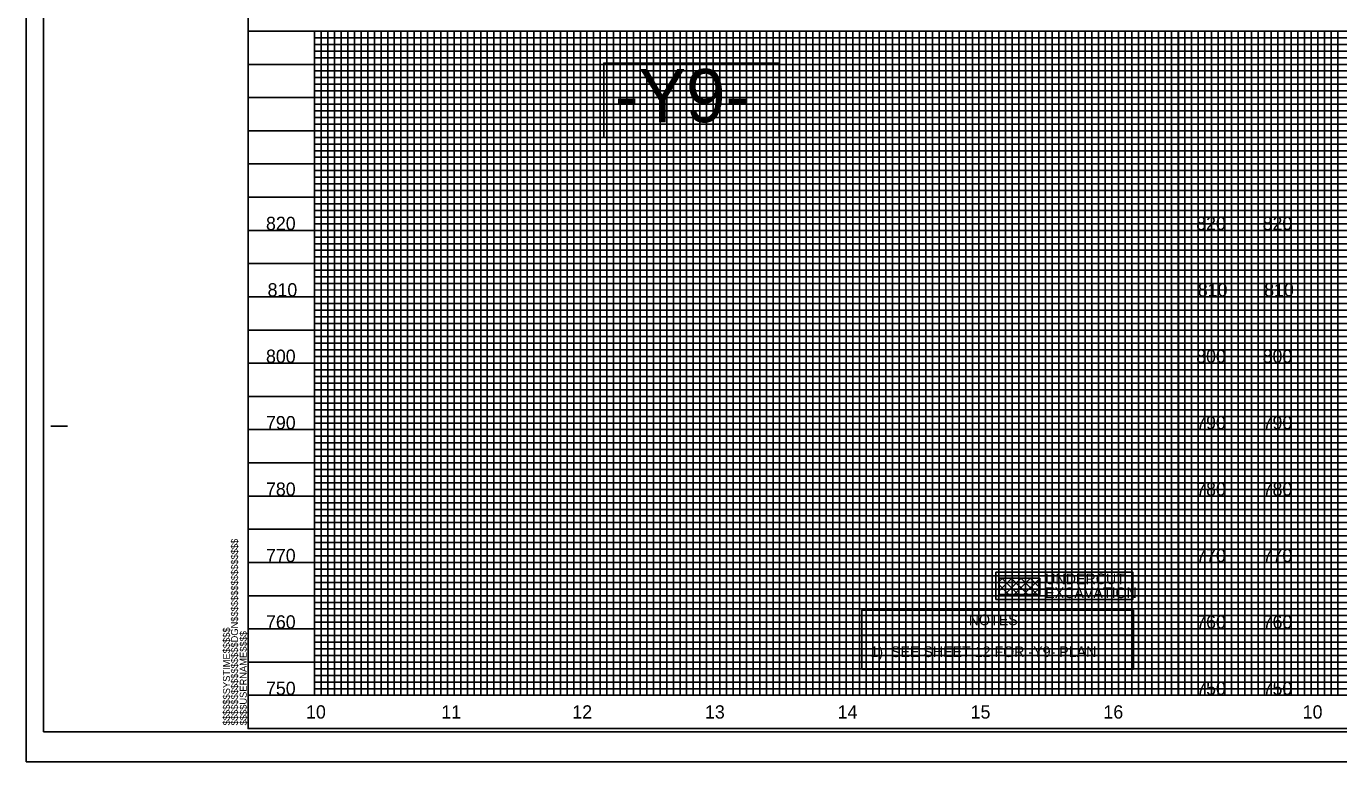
# Model space of a CAD drawing. Extents: x 600491 to 602382, y -54561 to -53461.
# Drawn here: x 600491 to 601479, y -54561 to -54007 of the extents above; entities that cross this region are included whole.
import ezdxf

# ---------------------------------------------------------------- set-up
doc = ezdxf.new("R2010")
doc.units = 0
for name, color, linetype in [('Default', 7, 'Continuous'), ('Exist Vertical Profile Horizontal Axis Label Major', 7, 'Continuous'), ('Exist Vertical Profile Vertical Axis Label', 7, 'Continuous'), ('Prop DSN Text', 7, 'Continuous'), ('Prop Grid Mask', 7, 'Continuous'), ('Prop VPI Label', 7, 'Continuous'), ('Prop XS Undercut Exc Hatch', 7, 'Continuous'), ('Prop XSC Text', 7, 'Continuous'), ('Sheet Cutting Line CELL', 7, 'Continuous'), ('Sheet DOT Grid CELL', 7, 'Continuous'), ('Sheet Layout Profile Border Port 2', 7, 'Continuous'), ('Sheet Plot Border Inside CELL', 7, 'Continuous'), ('Sheet Plot Border Outside CELL', 7, 'Continuous'), ('Sheet Profile CELL', 7, 'Continuous'), ('Sheet Profile Grid Major CELL', 7, 'Continuous'), ('Sheet Profile Grid Middle CELL', 7, 'Continuous'), ('Sheet Profile Grid Minor CELL', 7, 'Continuous')]:
    doc.layers.add(name, color=color, linetype=linetype)

msp = doc.modelspace()

# ---------------------------------------------------------------- linework, layer by layer
at = {"layer": 'Default'}
for points in [[(600708.27, -54010.99), (601358.32, -54010.99), (601358.32, -54510.99), (600708.27, -54510.99)], [(601458.32, -54010.99), (601708.27, -54010.99), (601708.27, -54510.99), (601458.32, -54510.99)]]:
    msp.add_lwpolyline(points, close=True, dxfattribs=at)
at = {"layer": 'Prop Grid Mask'}
for p, q in [((601358.32, -54035.99), (601408.32, -54035.99)), ((601408.32, -54035.99), (601458.32, -54035.99)), ((601358.32, -54060.99), (601408.32, -54060.99)), ((601408.32, -54060.99), (601458.32, -54060.99)), ((601358.32, -54085.99), (601408.32, -54085.99)), ((601408.32, -54085.99), (601458.32, -54085.99)), ((601358.32, -54110.99), (601408.32, -54110.99)), ((601408.32, -54110.99), (601458.32, -54110.99)), ((601358.32, -54135.99), (601408.32, -54135.99)), ((601408.32, -54135.99), (601458.32, -54135.99)), ((601358.32, -54160.99), (601408.32, -54160.99)), ((601408.32, -54160.99), (601458.32, -54160.99)), ((601358.32, -54185.99), (601408.32, -54185.99)), ((601408.32, -54185.99), (601458.32, -54185.99)), ((601358.32, -54210.99), (601408.32, -54210.99)), ((601408.32, -54210.99), (601458.32, -54210.99)), ((601358.32, -54235.99), (601408.32, -54235.99)), ((601408.32, -54235.99), (601458.32, -54235.99)), ((601358.32, -54260.99), (601408.32, -54260.99)), ((601408.32, -54260.99), (601458.32, -54260.99)), ((601358.32, -54285.99), (601408.32, -54285.99)), ((601408.32, -54285.99), (601458.32, -54285.99)), ((601358.32, -54310.99), (601408.32, -54310.99)), ((601408.32, -54310.99), (601458.32, -54310.99)), ((601358.32, -54335.99), (601408.32, -54335.99)), ((601408.32, -54335.99), (601458.32, -54335.99)), ((601358.32, -54360.99), (601408.32, -54360.99)), ((601408.32, -54360.99), (601458.32, -54360.99)), ((601358.32, -54385.99), (601408.32, -54385.99)), ((601408.32, -54385.99), (601458.32, -54385.99)), ((601358.32, -54410.99), (601408.32, -54410.99)), ((601408.32, -54410.99), (601458.32, -54410.99)), ((601358.32, -54435.99), (601408.32, -54435.99)), ((601408.32, -54435.99), (601458.32, -54435.99)), ((601358.32, -54460.99), (601408.32, -54460.99)), ((601408.32, -54460.99), (601458.32, -54460.99)), ((601358.32, -54485.99), (601408.32, -54485.99)), ((601408.32, -54485.99), (601458.32, -54485.99))]:
    msp.add_line(p, q, dxfattribs=at)
for points in [[(601358.32, -54010.99), (601408.32, -54010.99), (601408.32, -54510.99), (601358.32, -54510.99)], [(601408.32, -54010.99), (601458.32, -54010.99), (601458.32, -54510.99), (601408.32, -54510.99)], [(600925.94, -54091.06), (601057.96, -54091.06), (601057.96, -54035.01), (600925.94, -54035.01)], [(601221.02, -54418.33), (601324.1, -54418.33), (601324.1, -54438.8), (601221.02, -54438.8)], [(601223.44, -54435.15), (601253.95, -54435.15), (601253.95, -54422.82), (601223.44, -54422.82)], [(601120.11, -54491.28), (601324.46, -54491.28), (601324.46, -54446.99), (601120.11, -54446.99)], [(601120.11, -54465.71), (601324.46, -54465.71), (601324.46, -54446.99), (601120.11, -54446.99)]]:
    msp.add_lwpolyline(points, close=True, dxfattribs=at)
at = {"layer": 'Prop XS Undercut Exc Hatch'}
for p, q in [((601223.44, -54425.26), (601225.89, -54422.82)), ((601223.44, -54432.34), (601232.96, -54422.82)), ((601225.55, -54422.82), (601237.88, -54435.15)), ((601227.7, -54435.15), (601240.03, -54422.82)), ((601232.62, -54422.82), (601244.95, -54435.15)), ((601234.77, -54435.15), (601247.1, -54422.82)), ((601239.69, -54422.82), (601252.02, -54435.15)), ((601241.84, -54435.15), (601253.95, -54423.04)), ((601246.76, -54422.82), (601253.95, -54430)), ((601253.83, -54422.82), (601253.95, -54422.93)), ((601223.44, -54427.78), (601230.81, -54435.15)), ((601223.44, -54434.85), (601223.74, -54435.15)), ((601248.91, -54435.15), (601253.95, -54430.12))]:
    msp.add_line(p, q, dxfattribs=at)
at = {"layer": 'Sheet Cutting Line CELL'}
for p, q in [((600491.27, -53460.99), (600491.27, -54560.99)), ((600491.27, -54560.99), (602175.27, -54560.99))]:
    msp.add_line(p, q, dxfattribs=at)
at = {"layer": 'Sheet DOT Grid CELL'}
for p, q in [((600658.27, -54010.99), (602158.16, -54010.99)), ((600708.27, -54010.99), (600708.27, -54510.99)), ((600758.27, -54010.99), (600758.27, -54510.99)), ((600808.27, -54010.99), (600808.27, -54510.99)), ((600858.27, -54010.99), (600858.27, -54510.99)), ((600908.27, -54010.99), (600908.27, -54510.99)), ((600958.27, -54010.99), (600958.27, -54510.99)), ((601008.27, -54010.99), (601008.27, -54510.99)), ((601058.27, -54010.99), (601058.27, -54510.99)), ((601108.27, -54010.99), (601108.27, -54510.99)), ((601158.27, -54010.99), (601158.27, -54510.99)), ((601208.27, -54010.99), (601208.27, -54510.99)), ((601258.27, -54010.99), (601258.27, -54510.99)), ((601308.27, -54010.99), (601308.27, -54510.99)), ((601358.27, -54010.99), (601358.27, -54510.99)), ((601408.27, -54010.99), (601408.27, -54510.99)), ((601458.27, -54010.99), (601458.27, -54510.99)), ((600658.27, -54060.99), (602158.16, -54060.99)), ((600658.27, -54110.99), (602158.16, -54110.99)), ((600658.27, -54160.99), (602158.16, -54160.99)), ((600658.27, -54210.99), (602158.16, -54210.99)), ((600658.27, -54260.99), (602158.16, -54260.99)), ((600658.27, -54310.99), (602158.16, -54310.99)), ((600658.27, -54360.99), (602158.16, -54360.99)), ((600658.27, -54410.99), (602158.16, -54410.99)), ((600658.27, -54460.99), (602158.16, -54460.99))]:
    msp.add_line(p, q, dxfattribs=at)
at = {"layer": 'Sheet Layout Profile Border Port 2'}
for points in [[(600708.27, -54010.99), (601358.27, -54010.99), (601358.27, -54510.99), (600708.27, -54510.99)], [(601458.27, -54510.99), (601708.27, -54510.99), (601708.27, -54010.99), (601458.27, -54010.99)]]:
    msp.add_lwpolyline(points, close=True, dxfattribs=at)
at = {"layer": 'Sheet Plot Border Inside CELL'}
msp.add_lwpolyline([(600504.27, -54538.54), (602170.77, -54538.54), (602170.77, -53483.44), (600504.27, -53483.44)], close=True, dxfattribs=at)
at = {"layer": 'Sheet Plot Border Outside CELL'}
msp.add_lwpolyline([(600491.27, -54560.99), (602175.27, -54560.99), (602175.27, -53460.99), (600491.27, -53460.99)], close=True, dxfattribs=at)
at = {"layer": 'Sheet Profile CELL'}
for p, q in [((600658.27, -54010.99), (602158.27, -54010.99)), ((600509.77, -54308.49), (600522.27, -54308.49)), ((602158.27, -54510.99), (600658.27, -54510.99)), ((600658.27, -54535.99), (602158.27, -54535.99)), ((600658.27, -54535.99), (600658.27, -54535.99)), ((600658.27, -54535.99), (600658.27, -54535.99)), ((600658.27, -54535.99), (600658.27, -54535.99)), ((600658.27, -54535.99), (600658.27, -54535.99)), ((600658.27, -54535.99), (600658.27, -54535.99)), ((600658.27, -54535.99), (600658.27, -54535.99)), ((600658.27, -54535.99), (600658.27, -54535.99))]:
    msp.add_line(p, q, dxfattribs=at)
msp.add_lwpolyline([(602158.27, -53485.99), (600658.27, -53485.99), (600658.27, -54535.99), (602158.27, -54535.99)], close=True, dxfattribs=at)
msp.add_lwpolyline([(600695.77, -54535.99), (600695.77, -54535.99)], dxfattribs=at)
at = {"layer": 'Sheet Profile Grid Major CELL'}
for p, q in [((601158.27, -54010.99), (601208.27, -54010.99)), ((601258.27, -54010.99), (601308.27, -54010.99)), ((601358.27, -54010.99), (601408.27, -54010.99)), ((601458.27, -54010.99), (601508.27, -54010.99)), ((600658.27, -54510.99), (600658.27, -54510.99))]:
    msp.add_line(p, q, dxfattribs=at)
for points in [[(600708.27, -54010.99), (600708.27, -54510.99), (600758.27, -54510.99), (600758.27, -54010.99), (600808.27, -54010.99), (600808.27, -54510.99), (600858.27, -54510.99), (600858.27, -54010.99), (600908.27, -54010.99), (600908.27, -54510.99), (600958.27, -54510.99), (600958.27, -54010.99), (601008.27, -54010.99), (601008.27, -54510.99), (601058.27, -54510.99), (601058.27, -54010.99), (601108.27, -54010.99), (601108.27, -54510.99), (601158.27, -54510.99), (601158.27, -54010.99), (601208.27, -54010.99), (601208.27, -54510.99), (601258.27, -54510.99), (601258.27, -54010.99), (601308.27, -54010.99), (601308.27, -54510.99), (601358.27, -54510.99), (601358.27, -54010.99), (601408.27, -54010.99), (601408.27, -54510.99), (601458.27, -54510.99), (601458.27, -54010.99), (601508.27, -54010.99)], [(602158.27, -54060.99), (600658.27, -54060.99)], [(602158.27, -54110.99), (600658.27, -54110.99), (600658.27, -54160.99), (602158.27, -54160.99)], [(602158.27, -54210.99), (600658.27, -54210.99), (600658.27, -54260.99), (602158.27, -54260.99)], [(602158.27, -54310.99), (600658.27, -54310.99), (600658.27, -54360.99), (602158.27, -54360.99)], [(602158.27, -54410.99), (600658.27, -54410.99), (600658.27, -54410.99), (600658.27, -54460.99), (602158.27, -54460.99)], [(602158.27, -54510.99), (600658.27, -54510.99)]]:
    msp.add_lwpolyline(points, dxfattribs=at)
at = {"layer": 'Sheet Profile Grid Middle CELL'}
for points in [[(600683.27, -54010.99), (600733.27, -54010.99), (600733.27, -54510.99), (600783.27, -54510.99), (600783.27, -54010.99), (600833.27, -54010.99), (600833.27, -54510.99), (600883.27, -54510.99), (600883.27, -54010.99), (600933.27, -54010.99), (600933.27, -54510.99), (600983.27, -54510.99), (600983.27, -54010.99), (601033.27, -54010.99), (601033.27, -54510.99), (601083.27, -54510.99), (601083.27, -54010.99), (601133.27, -54010.99), (601133.27, -54510.99), (601183.27, -54510.99), (601183.27, -54010.99), (601233.27, -54010.99), (601233.27, -54510.99), (601283.27, -54510.99), (601283.27, -54510.99), (601283.27, -54010.99), (601333.27, -54010.99), (601333.27, -54510.99), (601383.27, -54510.99), (601383.27, -54010.99), (601433.27, -54010.99), (601433.27, -54510.99), (601483.27, -54510.99)], [(600658.27, -54035.99), (602158.27, -54035.99)], [(602158.27, -54085.99), (600658.27, -54085.99), (600658.27, -54135.99), (602158.27, -54135.99)], [(602158.27, -54185.99), (600658.27, -54185.99), (600658.27, -54235.99), (602158.27, -54235.99)], [(602158.27, -54285.99), (600658.27, -54285.99), (600658.27, -54335.99), (602158.27, -54335.99)], [(602158.27, -54385.99), (600658.27, -54385.99), (600658.27, -54435.99), (602158.27, -54435.99)], [(602158.27, -54485.99), (600658.27, -54485.99)]]:
    msp.add_lwpolyline(points, dxfattribs=at)
at = {"layer": 'Sheet Profile Grid Minor CELL'}
for p, q in [((600708.27, -54015.99), (602108.27, -54015.99)), ((602108.27, -54020.99), (600708.27, -54020.99)), ((600708.27, -54025.99), (602108.27, -54025.99)), ((602108.27, -54030.99), (600708.27, -54030.99)), ((600708.27, -54040.99), (602108.27, -54040.99)), ((602108.27, -54045.99), (600708.27, -54045.99)), ((600708.27, -54050.99), (602108.27, -54050.99)), ((602108.27, -54055.99), (600708.27, -54055.99)), ((600708.27, -54065.99), (602108.27, -54065.99)), ((602108.27, -54070.99), (600708.27, -54070.99)), ((600708.27, -54075.99), (602108.27, -54075.99)), ((602108.27, -54080.99), (600708.27, -54080.99)), ((600708.27, -54090.99), (602108.27, -54090.99)), ((602108.27, -54095.99), (600708.27, -54095.99)), ((600708.27, -54100.99), (602108.27, -54100.99)), ((602108.27, -54105.99), (600708.27, -54105.99)), ((600708.27, -54115.99), (602108.27, -54115.99)), ((602108.27, -54120.99), (600708.27, -54120.99)), ((600708.27, -54125.99), (602108.27, -54125.99)), ((602108.27, -54130.99), (600708.27, -54130.99)), ((600708.27, -54140.99), (602108.27, -54140.99)), ((602108.27, -54145.99), (600708.27, -54145.99)), ((600708.27, -54150.99), (602108.27, -54150.99)), ((602108.27, -54155.99), (600708.27, -54155.99)), ((600708.27, -54165.99), (602108.27, -54165.99)), ((602108.27, -54170.99), (600708.27, -54170.99)), ((600708.27, -54175.99), (602108.27, -54175.99)), ((602108.27, -54180.99), (600708.27, -54180.99)), ((600708.27, -54190.99), (602108.27, -54190.99)), ((602108.27, -54195.99), (600708.27, -54195.99)), ((600708.27, -54200.99), (602108.27, -54200.99)), ((602108.27, -54205.99), (600708.27, -54205.84)), ((600708.27, -54215.99), (602108.27, -54215.99)), ((602108.27, -54220.99), (600708.27, -54220.99)), ((600708.27, -54225.99), (602108.27, -54225.99)), ((602108.27, -54230.99), (600708.27, -54230.99)), ((600708.27, -54240.99), (602108.27, -54240.99)), ((602108.27, -54245.99), (600708.27, -54245.99)), ((600708.27, -54250.99), (602108.27, -54250.99)), ((602108.27, -54255.99), (600708.27, -54255.99)), ((600708.27, -54265.99), (602108.27, -54265.99)), ((602108.27, -54270.99), (600708.27, -54270.99)), ((600708.27, -54275.99), (602108.27, -54275.99)), ((602108.27, -54280.99), (600708.27, -54280.99)), ((600708.27, -54290.99), (602108.27, -54290.99)), ((602108.27, -54295.99), (600708.27, -54295.99)), ((600708.27, -54300.99), (602108.27, -54300.99)), ((602108.27, -54305.99), (600708.27, -54305.99)), ((600708.27, -54315.99), (602108.27, -54315.99)), ((602108.27, -54320.99), (600708.27, -54320.99)), ((600708.27, -54325.99), (602108.27, -54325.99)), ((602108.27, -54330.99), (600708.27, -54330.99)), ((600708.27, -54340.99), (602108.27, -54340.99)), ((602108.27, -54345.99), (600708.27, -54345.99)), ((600708.27, -54350.99), (602108.27, -54350.99)), ((602108.27, -54355.99), (600708.27, -54355.99)), ((600708.27, -54365.99), (602108.27, -54365.99)), ((602108.27, -54370.99), (600708.27, -54370.99)), ((600708.27, -54375.99), (602108.27, -54375.99)), ((602108.27, -54380.99), (600708.27, -54380.99)), ((600708.27, -54390.99), (602108.27, -54390.99)), ((602108.27, -54395.99), (600708.27, -54395.99)), ((600708.27, -54400.99), (602108.27, -54400.99)), ((602108.27, -54405.99), (600708.27, -54405.99)), ((600708.27, -54415.99), (602108.27, -54415.99)), ((602108.27, -54420.99), (600708.27, -54420.99)), ((600708.27, -54425.99), (602108.27, -54425.99)), ((602108.27, -54430.99), (600708.27, -54430.99)), ((600708.27, -54440.99), (602108.27, -54440.99)), ((602108.27, -54445.99), (600708.27, -54445.99)), ((600708.27, -54450.99), (602108.27, -54450.99)), ((602108.27, -54455.99), (600708.27, -54455.99)), ((600708.27, -54465.99), (602108.27, -54465.99)), ((602108.27, -54470.99), (600708.27, -54470.99)), ((600708.27, -54475.99), (602108.27, -54475.99)), ((602108.27, -54480.99), (600708.27, -54480.99)), ((600708.27, -54490.99), (602108.27, -54490.99)), ((602108.27, -54495.99), (600708.27, -54495.99)), ((600708.27, -54500.99), (602108.27, -54500.99)), ((600708.27, -54505.99), (602108.27, -54505.99))]:
    msp.add_line(p, q, dxfattribs=at)
for points in [[(600708.27, -54010.99), (600713.27, -54010.99), (600713.27, -54510.99), (600718.27, -54510.99), (600718.27, -54010.99), (600723.27, -54010.99), (600723.27, -54510.99), (600728.27, -54510.99), (600728.27, -54010.99), (600738.27, -54010.99), (600738.27, -54510.99), (600743.27, -54510.99), (600743.27, -54010.99), (600748.27, -54010.99), (600748.27, -54510.99), (600753.27, -54510.99), (600763.27, -54510.99), (600768.27, -54510.99), (600768.27, -54010.99), (600773.27, -54010.99), (600773.27, -54510.99), (600778.27, -54510.99), (600778.27, -54010.99), (600788.27, -54010.99), (600788.27, -54510.99), (600793.27, -54510.99), (600793.27, -54010.99), (600798.27, -54010.99), (600798.27, -54510.99), (600803.27, -54510.99), (600803.27, -54010.99), (600813.27, -54010.99), (600813.27, -54510.99), (600818.27, -54510.99), (600818.27, -54010.99), (600823.27, -54010.99), (600823.27, -54510.99), (600828.27, -54510.99), (600828.27, -54010.99), (600838.27, -54010.99), (600838.27, -54510.99), (600843.27, -54510.99), (600843.27, -54010.99), (600848.27, -54010.99), (600848.27, -54510.99), (600853.27, -54510.99), (600853.27, -54010.99), (600863.27, -54010.99), (600863.27, -54510.99), (600868.27, -54510.99), (600868.27, -54010.99), (600873.27, -54010.99), (600873.27, -54510.99), (600878.27, -54510.99), (600878.27, -54010.99), (600888.27, -54010.99), (600888.27, -54510.99), (600893.27, -54510.99), (600893.27, -54010.99), (600898.27, -54010.99), (600898.27, -54510.99), (600903.27, -54510.99), (600903.27, -54010.99), (600913.27, -54010.99), (600913.27, -54510.99), (600918.27, -54510.99), (600918.27, -54010.99), (600923.27, -54010.99), (600923.27, -54510.99)], [(600753.27, -54510.99), (600753.27, -54010.99), (600763.27, -54010.99), (600763.27, -54510.99)], [(600923.27, -54510.99), (600928.27, -54510.99), (600928.27, -54010.99), (600938.27, -54010.99), (600938.27, -54510.99), (600943.27, -54510.99), (600943.27, -54010.99), (600948.27, -54010.99), (600948.27, -54510.99), (600953.27, -54510.99), (600953.27, -54010.99), (600963.27, -54010.99), (600963.27, -54510.99), (600968.27, -54510.99), (600968.27, -54010.99), (600973.27, -54010.99), (600973.27, -54510.99), (600978.27, -54510.99), (600978.27, -54010.99), (600988.27, -54010.99), (600988.27, -54510.99), (600993.27, -54510.99), (600993.27, -54010.99), (600998.27, -54010.99), (600998.27, -54510.99), (601003.27, -54510.99), (601003.27, -54010.99), (601013.27, -54010.99), (601013.27, -54510.99), (601018.27, -54510.99), (601018.27, -54010.99), (601023.27, -54010.99), (601023.27, -54510.99), (601028.27, -54510.99), (601028.27, -54010.99), (601038.27, -54010.99), (601038.27, -54510.99), (601043.27, -54510.99), (601043.27, -54010.99), (601048.27, -54010.99), (601048.27, -54510.99), (601053.27, -54510.99), (601053.27, -54010.99), (601063.27, -54010.99), (601063.27, -54510.99), (601068.27, -54510.99), (601068.27, -54010.99), (601073.27, -54010.99), (601073.27, -54510.99), (601078.27, -54510.99), (601078.27, -54010.99), (601088.27, -54010.99), (601088.27, -54510.99), (601093.27, -54510.99), (601093.27, -54010.99), (601098.27, -54010.99), (601098.27, -54510.99), (601103.27, -54510.99), (601103.27, -54010.99), (601113.27, -54010.99), (601113.27, -54510.99), (601118.27, -54510.99), (601118.27, -54010.99), (601123.27, -54010.99), (601123.27, -54510.99), (601128.27, -54510.99), (601128.27, -54010.99), (601138.27, -54010.99), (601138.27, -54510.99), (601143.27, -54510.99), (601143.27, -54010.99), (601148.27, -54010.99), (601148.27, -54510.99), (601153.27, -54510.99), (601153.27, -54010.99), (601163.27, -54010.99), (601163.27, -54510.99), (601168.27, -54510.99), (601168.27, -54010.99), (601173.27, -54010.99), (601173.27, -54510.99), (601178.27, -54510.99), (601178.27, -54010.99), (601188.27, -54010.99), (601188.27, -54510.99), (601193.27, -54510.99), (601193.27, -54010.99), (601198.27, -54010.99), (601198.27, -54510.99), (601203.27, -54510.99), (601203.27, -54010.99), (601213.27, -54010.99), (601213.27, -54510.99), (601218.27, -54510.99), (601218.27, -54010.99), (601223.27, -54010.99), (601223.27, -54510.99), (601228.27, -54510.99), (601228.27, -54010.99), (601238.27, -54010.99)], [(601238.27, -54010.99), (601238.27, -54510.99), (601243.27, -54510.99), (601243.27, -54010.99), (601248.27, -54010.99), (601248.27, -54510.99), (601253.27, -54510.99), (601253.27, -54010.99), (601263.27, -54010.99), (601263.27, -54510.99), (601268.27, -54510.99), (601268.27, -54010.99), (601273.27, -54010.99), (601273.27, -54510.99), (601278.27, -54510.99), (601278.27, -54010.99), (601288.27, -54010.99), (601288.27, -54510.99), (601293.27, -54510.99), (601293.27, -54010.99), (601298.27, -54010.99), (601298.27, -54510.99), (601303.27, -54510.99), (601303.27, -54010.99), (601313.27, -54010.99), (601313.27, -54510.99), (601318.27, -54510.99), (601318.27, -54010.99), (601323.27, -54010.99), (601323.27, -54510.99), (601328.27, -54510.99), (601328.27, -54010.99), (601338.27, -54010.99), (601338.27, -54510.99), (601343.27, -54510.99), (601343.27, -54010.99), (601348.27, -54010.99), (601348.27, -54510.99), (601353.27, -54510.99), (601353.27, -54010.99), (601363.27, -54010.99), (601363.27, -54510.99), (601363.27, -54510.99), (601368.27, -54510.99), (601368.27, -54010.99), (601373.27, -54010.99), (601373.27, -54510.99), (601378.27, -54510.99), (601378.27, -54010.99), (601388.27, -54010.99), (601388.27, -54510.99), (601393.27, -54510.99), (601393.27, -54010.99), (601398.27, -54010.99), (601398.27, -54510.99), (601403.27, -54510.99), (601403.27, -54010.99), (601413.27, -54010.99), (601413.27, -54510.99), (601418.27, -54510.99), (601418.27, -54010.99), (601423.27, -54010.99), (601423.27, -54510.99), (601428.27, -54510.99), (601428.27, -54010.99), (601438.27, -54010.99), (601438.27, -54510.99), (601443.27, -54510.99), (601443.27, -54010.99), (601448.27, -54010.99), (601448.27, -54510.99), (601453.27, -54510.99), (601453.27, -54010.99), (601463.27, -54010.99), (601463.27, -54510.99), (601468.27, -54510.99), (601468.27, -54010.99), (601473.27, -54010.99), (601473.27, -54510.99), (601478.27, -54510.99), (601478.27, -54010.99), (601488.27, -54010.99)]]:
    msp.add_lwpolyline(points, dxfattribs=at)

# ---------------------------------------------------------------- texts
at = {"layer": 'Exist Vertical Profile Horizontal Axis Label Major'}
for s, p in [('10', (600701.86, -54528.49)), ('11', (600803.7, -54528.49)), ('12', (600902.24, -54528.49)), ('13', (601002.08, -54528.49)), ('14', (601101.92, -54528.49)), ('15', (601202.01, -54528.49)), ('16', (601301.95, -54528.49)), ('10', (601451.91, -54528.49))]:
    msp.add_text(s, height=10, dxfattribs=at).set_placement(p)
at = {"layer": 'Exist Vertical Profile Vertical Axis Label'}
for s, p in [('820', (600671.7, -54160.74)), ('820', (601371.75, -54160.74)), ('820', (601421.75, -54160.74)), ('810', (600672.9, -54210.74)), ('810', (601372.95, -54210.74)), ('810', (601422.95, -54210.74)), ('800', (600671.7, -54260.74)), ('800', (601371.75, -54260.74)), ('800', (601421.75, -54260.74)), ('790', (600671.7, -54310.74)), ('790', (601371.75, -54310.74)), ('790', (601421.75, -54310.74)), ('780', (600671.7, -54360.74)), ('780', (601371.75, -54360.74)), ('780', (601421.75, -54360.74)), ('770', (600671.7, -54410.74)), ('770', (601371.75, -54410.74)), ('770', (601421.75, -54410.74)), ('760', (600671.7, -54460.74)), ('760', (601371.75, -54460.74)), ('760', (601421.75, -54460.74)), ('750', (600671.7, -54510.74)), ('750', (601371.75, -54510.74)), ('750', (601421.75, -54510.74))]:
    msp.add_text(s, height=10, dxfattribs=at).set_placement(p)
at = {"layer": 'Prop DSN Text'}
for s, p in [('NOTES', (601200.54, -54458.18)), ('1)  SEE SHEET 12 FOR -Y9- PLAN', (601126.59, -54482.18))]:
    msp.add_text(s, height=8, dxfattribs=at).set_placement(p)
at = {"layer": 'Prop VPI Label'}
msp.add_text('-Y9-', height=40, dxfattribs=at).set_placement((600934.25, -54079.56))
at = {"layer": 'Prop XSC Text'}
for s, p in [('UNDERCUT', (601258.09, -54427.32)), ('EXCAVATION', (601258.09, -54437.81))]:
    msp.add_text(s, height=8, dxfattribs=at).set_placement(p)
at = {"layer": 'Sheet Profile CELL'}
for s, p in [('$$$$$$$$$$$$$$$$DGN$$$$$$$$$$$$$$$$', (600650.64, -54533.62)), ('$$$$$$SYSTIME$$$$$', (600644.59, -54533.62)), ('$$$$USERNAME$$$$', (600657.21, -54533.61))]:
    msp.add_text(s, height=5.25, rotation=90, dxfattribs=at).set_placement(p)

doc.saveas('drawing.dxf')
